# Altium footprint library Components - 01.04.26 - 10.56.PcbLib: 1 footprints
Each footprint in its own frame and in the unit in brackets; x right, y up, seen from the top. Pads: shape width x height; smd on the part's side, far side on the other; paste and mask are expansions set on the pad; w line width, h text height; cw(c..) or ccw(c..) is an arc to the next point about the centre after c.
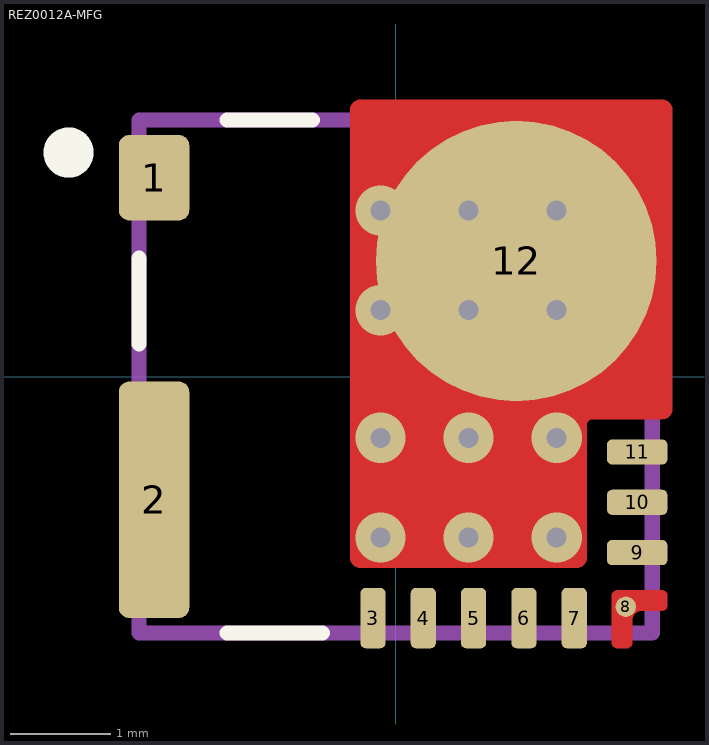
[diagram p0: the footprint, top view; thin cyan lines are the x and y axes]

## REZ0012A-MFG [mm]
pads (12):
  rrect29% 0.7x0.85 smd paste-1000 mask-1000: 1(-2.4,1.975)
  rrect29% 0.7x2.35 smd paste-1000 mask-1000: 2(-2.4,-1.225)
  rrect40% 0.25x0.6 smd paste+0 mask+0: 3(-0.225,-2.4) 4(0.275,-2.4) 5(0.775,-2.4) 6(1.275,-2.4) 7(1.775,-2.4)
  round 0.203 smd paste+0 mask+0: 8(2.288,-2.288)
  rrect40% 0.6x0.25 smd paste+0 mask+0: 9(2.4,-1.75) 10(2.4,-1.25) 11(2.4,-0.75)
  round 2.788 smd paste-1000 mask-1000: 12(1.199,1.148)
via -0.15,1.65 diameter 0.5 hole 0.2
via 0.725,1.65 diameter 0.5 hole 0.2
via 1.6,1.65 diameter 0.5 hole 0.2
via 1.6,0.66 diameter 0.5 hole 0.2
via 0.725,0.66 diameter 0.5 hole 0.2
via -0.15,0.66 diameter 0.5 hole 0.2
via 1.6,-0.61 diameter 0.5 hole 0.2
via 0.725,-0.61 diameter 0.5 hole 0.2
via -0.15,-0.61 diameter 0.5 hole 0.2
via 1.6,-1.6 diameter 0.5 hole 0.2
via 0.725,-1.6 diameter 0.5 hole 0.2
via -0.15,-1.6 diameter 0.5 hole 0.2
Top Layer:
  region: 2.2,-2.7 2.19,-2.7 2.172,-2.692 2.158,-2.678 2.15,-2.66 2.15,-2.65 2.15,-2.175 2.15,-2.165 2.158,-2.147 2.172,-2.133 2.19,-2.125 2.2,-2.125 2.65,-2.125 2.66,-2.125 2.678,-2.133 2.692,-2.147 2.7,-2.165 2.7,-2.175 2.7,-2.275 2.7,-2.285 2.692,-2.303 2.678,-2.317 2.66,-2.325 2.65,-2.325 2.45,-2.325 2.43,-2.327 2.394,-2.342 2.367,-2.369 2.352,-2.405 2.35,-2.425 2.35,-2.65 2.35,-2.66 2.342,-2.678 2.328,-2.692 2.31,-2.7 2.3,-2.7
  region: -0.45,2.65 -0.45,2.67 -0.435,2.707 -0.407,2.735 -0.37,2.75 -0.35,2.75 2.648,2.75 2.668,2.75 2.705,2.735 2.733,2.707 2.748,2.67 2.748,2.65 2.748,-0.325 2.748,-0.345 2.733,-0.382 2.705,-0.41 2.668,-0.425 2.648,-0.425 1.95,-0.425 1.94,-0.426 1.922,-0.433 1.908,-0.447 1.901,-0.465 1.9,-0.475 1.9,-1.8 1.9,-1.82 1.885,-1.857 1.857,-1.885 1.82,-1.9 1.8,-1.9 -0.35,-1.9 -0.37,-1.9 -0.407,-1.885 -0.435,-1.857 -0.45,-1.82 -0.45,-1.8
Top Overlay:
  circle w0.25: c-3.25,2.225 r0.125
  lines w0.15: -2.55,0.325 -2.55,1.175 ; -1.675,-2.55 -0.725,-2.55 ; -1.675,2.55 -0.825,2.55
Top Paste:
  drawing of 20 lines, arcs and shapes, not listed
Top Solder:
  drawing of 4 lines, arcs and shapes, not listed
Mechanical 5:
  lines w0.15: -2.55,-2.55 2.55,-2.55 2.55,2.55 -2.55,2.55 -2.55,-2.55
  text ".Designator" at 0.049,0.242 h0.5
3D body "IC_UCG28826_VQFN12.STEP": height 0.25, standoff 0, extent -2.85,-2.8 2.848,2.85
